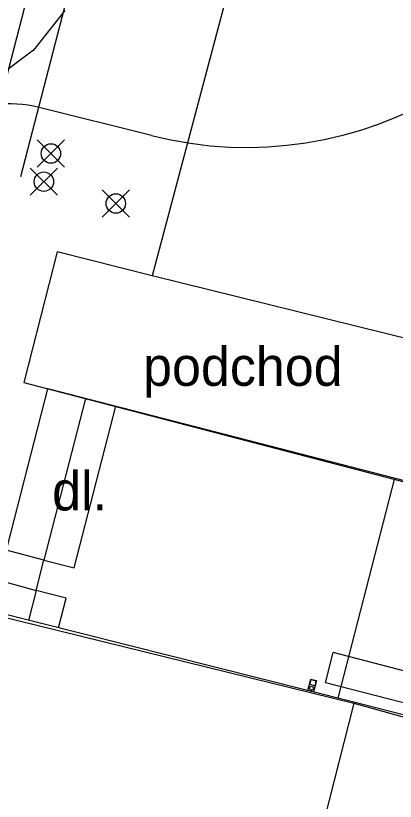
# Model space of a CAD drawing. Extents: x -733601 to -733291, y -1137892 to -1137187.
# Drawn here: x -733465.26 to -733455.49, y -1137651.84 to -1137631.66 of the extents above; entities that cross this region are included whole.
import ezdxf

# ---------------------------------------------------------------- set-up
doc = ezdxf.new("R2010")
doc.units = 0
for name, color, linetype in [('Default', 7, 'Continuous'), ('SIT_PROJ', 7, 'Continuous'), ('SIT_PUV_BUS', 7, 'Continuous'), ('SIT_PUV_ZELEZNICE', 7, 'Continuous')]:
    doc.layers.add(name, color=color, linetype=linetype)

# ---------------------------------------------------------------- blocks, each defined once
blk = doc.blocks.new('POINT_DISPLAY')
at = {"layer": 'Default'}
for p, q in [((-0.7, -0.7), (0.7, 0.7)), ((-0.7, 0.7), (0.7, -0.7))]:
    blk.add_line(p, q, dxfattribs=at)
blk.add_circle((0, 0), 0.5, dxfattribs=at)
blk = doc.blocks.new('vytyc_bod_MP')
at = {"layer": 'Default'}
blk.add_blockref('POINT_DISPLAY', (0, 0), dxfattribs=at)

msp = doc.modelspace()

# ---------------------------------------------------------------- linework, layer by layer
at = {"layer": 'SIT_PROJ'}
for points in [[(-733463.07, -1137623.85), (-733466.099, -1137635.551)], [(-733462.101, -1137624.1), (-733465.131, -1137635.801)], [(-733461.765, -1137634.741), (-733464.65, -1137634.017)]]:
    msp.add_lwpolyline(points, dxfattribs=at)
for centre, radius, start, end in [((-733459.33, -1137625.042), 10, 255.9059, 345.9059), ((-733465.38, -1137636.926), 3, 75.9059, 162.4158)]:
    msp.add_arc(centre, radius, start, end, dxfattribs=at)
at = {"layer": 'SIT_PUV_BUS'}
for p, q in [((-733456.8, -1137619.8), (-733461.75, -1137638.34)), ((-733463.99, -1137631.53), (-733464.8, -1137632.55)), ((-733464.8, -1137632.55), (-733467.06, -1137634.23)), ((-733464.19, -1137637.73), (-733465.05, -1137641.08)), ((-733461.75, -1137638.34), (-733464.19, -1137637.73)), ((-733454.56, -1137640.12), (-733461.75, -1137638.34)), ((-733465.05, -1137641.08), (-733455.14, -1137643.67)), ((-733466.17, -1137646.96), (-733456.56, -1137649.32)), ((-733456.56, -1137649.32), (-733464.08, -1137678.93)), ((-733456.56, -1137649.32), (-733453.45, -1137650.19))]:
    msp.add_line(p, q, dxfattribs=at)
at = {"layer": 'SIT_PUV_ZELEZNICE'}
for p, q in [((-733465.899, -1137646.951), (-733464.426, -1137641.243)), ((-733455.227, -1137643.616), (-733464.426, -1137641.243)), ((-733463.458, -1137641.493), (-733464.53, -1137645.65)), ((-733463.756, -1137645.849), (-733462.683, -1137641.693)), ((-733455.518, -1137643.541), (-733456.976, -1137649.192)), ((-733464.53, -1137645.65), (-733465.497, -1137645.392)), ((-733464.73, -1137646.425), (-733464.53, -1137645.65)), ((-733464.73, -1137646.425), (-733464.929, -1137647.195)), ((-733463.956, -1137646.624), (-733464.73, -1137646.425)), ((-733464.153, -1137647.39), (-733463.956, -1137646.624)), ((-733457.293, -1137648.799), (-733457.095, -1137648.024)), ((-733452.626, -1137649.17), (-733457.095, -1137648.024)), ((-733452.824, -1137649.945), (-733457.293, -1137648.799))]:
    msp.add_line(p, q, dxfattribs=at)
for points in [[(-733464.53, -1137645.65), (-733463.756, -1137645.849)], [(-733465.696, -1137646.166), (-733464.73, -1137646.425)], [(-733462.935, -1137685.963), (-733461.332, -1137679.64), (-733453.759, -1137650.014), (-733456.593, -1137649.288), (-733465.899, -1137646.951)]]:
    msp.add_lwpolyline(points, dxfattribs=at)
for points in [[(-733457.595, -1137649.03), (-733457.741, -1137648.994), (-733457.668, -1137648.703), (-733457.522, -1137648.739)], [(-733457.566, -1137648.873), (-733457.692, -1137648.841), (-733457.661, -1137648.715), (-733457.534, -1137648.746)]]:
    msp.add_lwpolyline(points, close=True, dxfattribs=at)
msp.add_circle((-733457.65, -1137648.939), 0.05, dxfattribs=at)

# ---------------------------------------------------------------- block references
at = {"layer": 'SIT_PROJ', "xscale": 0.5, "yscale": 0.5}
for p in [(-733464.35, -1137635.201), (-733464.531, -1137635.925), (-733462.682, -1137636.485)]:
    msp.add_blockref('vytyc_bod_MP', p, dxfattribs=at)

# ---------------------------------------------------------------- texts
at = {"layer": 'SIT_PUV_BUS'}
for s, p in [('podchod', (-733461.98, -1137641.17)), ('dl.', (-733464.32, -1137644.37))]:
    msp.add_text(s, height=1, dxfattribs=at).set_placement(p)

doc.saveas('drawing.dxf')
